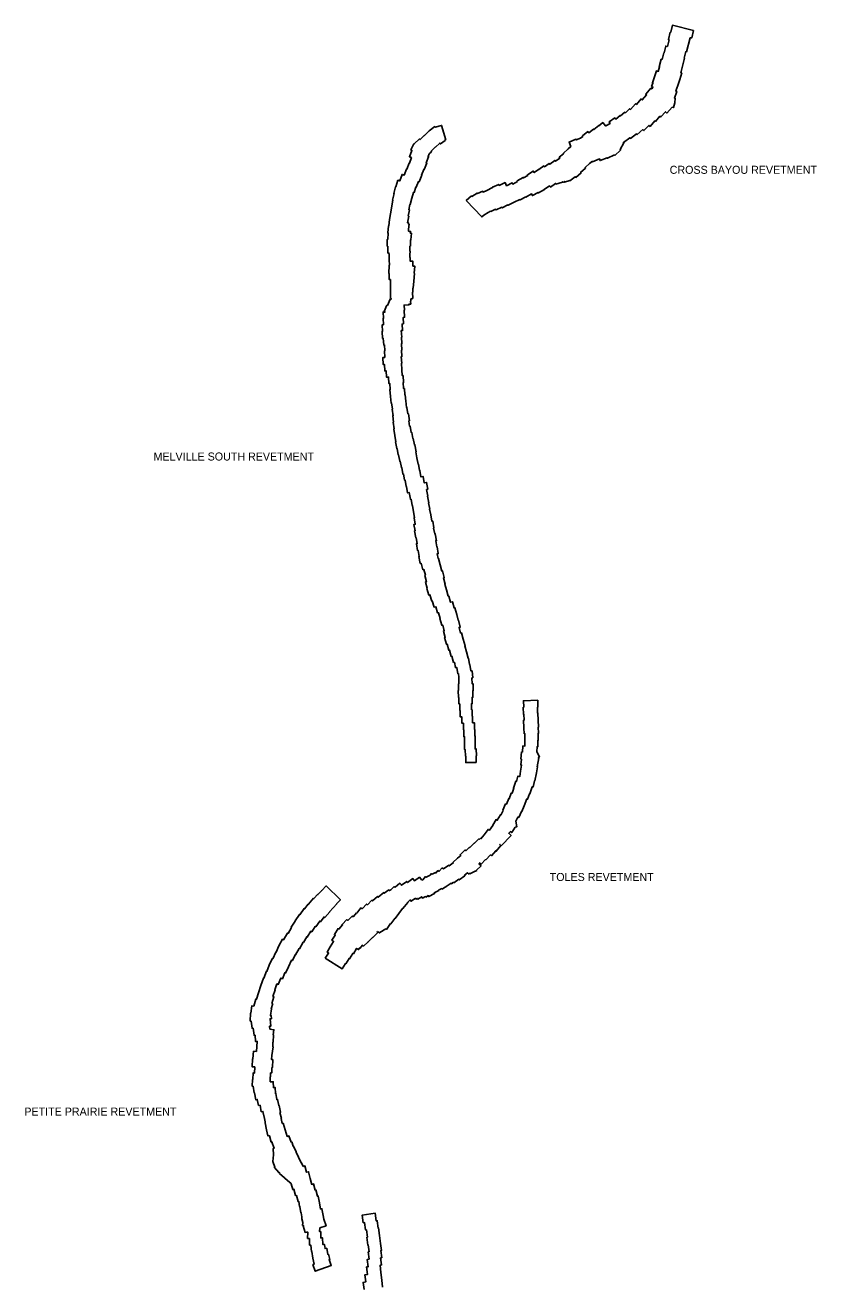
# Model space of a CAD drawing. Extents: x 2650582 to 3923188, y 277893 to 989177.
# Drawn here: x 3142897 to 3158735, y 764129 to 789359 of the extents above; entities that cross this region are included whole.
import ezdxf

# ---------------------------------------------------------------- set-up
doc = ezdxf.new("R2010")
doc.units = 0
doc.layers.add('Level 3', color=7, linetype='Continuous')

msp = doc.modelspace()

# ---------------------------------------------------------------- linework, layer by layer
at = {"layer": 'Level 3'}
for points in [[(3156270, 789256), (3156233, 789104), (3156204, 789110), (3156131, 788828), (3156112, 788832), (3156081, 788702), (3156086, 788701), (3156012, 788410), (3156033, 788404), (3155998, 788277), (3155956, 788154), (3155952, 788156), (3155914, 788044), (3155935, 788036), (3155887, 787901), (3155905, 787899), (3155896, 787808), (3155893, 787809), (3155866, 787712), (3155842, 787718), (3155738, 787601), (3155708, 787628), (3155616, 787524), (3155598, 787540), (3155507, 787434), (3155495, 787444), (3155400, 787335), (3155376, 787355), (3155275, 787251), (3155253, 787272), (3155141, 787171), (3155128, 787185), (3155011, 787094), (3154998, 787110), (3154865, 787014), (3154876, 787008), (3154801, 786871), (3154809, 786863), (3154697, 786755), (3154687, 786765), (3154546, 786699), (3154540, 786710), (3154401, 786653), (3154389, 786684), (3154250, 786627), (3154246, 786639)], [(3154506, 787347), (3154511, 787350), (3154514, 787344), (3154601, 787396), (3154580, 787425), (3154693, 787507), (3154712, 787481), (3154803, 787552), (3154810, 787544), (3154894, 787620), (3154911, 787608), (3154989, 787689), (3155011, 787677), (3155110, 787790), (3155127, 787775), (3155221, 787885), (3155243, 787866), (3155330, 787965), (3155313, 787980), (3155418, 788098), (3155433, 788084), (3155456, 788123), (3155429, 788134), (3155455, 788203), (3155446, 788206), (3155527, 788446), (3155564, 788434), (3155590, 788527), (3155583, 788529), (3155622, 788679), (3155641, 788674), (3155674, 788805), (3155679, 788804), (3155713, 788942), (3155748, 788934), (3155781, 789067), (3155767, 789071), (3155804, 789220), (3155812, 789218), (3155846, 789359), (3156270, 789256)], [(3150217, 783872), (3150217, 783896), (3150208, 783896), (3150206, 784161), (3150207, 784161), (3150205, 784274), (3150182, 784273), (3150179, 784392), (3150175, 784392), (3150177, 784559), (3150184, 784559), (3150181, 784669), (3150179, 784669), (3150178, 784786), (3150174, 784786), (3150174, 784802), (3150154, 784802), (3150152, 784938), (3150140, 784938), (3150142, 785075), (3150151, 785075), (3150157, 785205), (3150152, 785205), (3150165, 785347), (3150171, 785346), (3150189, 785471), (3150185, 785472), (3150206, 785586), (3150252, 785860), (3150245, 785862), (3150277, 785992), (3150272, 785993), (3150308, 786130), (3150311, 786129), (3150353, 786259), (3150392, 786247), (3150439, 786374), (3150477, 786360), (3150527, 786483), (3150534, 786480), (3150581, 786603), (3150584, 786602), (3150626, 786711), (3150584, 786728), (3150635, 786855), (3150614, 786866), (3150674, 786987), (3150681, 786984), (3150788, 787084), (3150798, 787073), (3150883, 787156), (3150886, 787153), (3150979, 787245), (3151092, 787331), (3151101, 787319), (3151227, 787357), (3151315, 787068)], [(3152748, 786231), (3152739, 786247), (3152862, 786314), (3152867, 786305), (3152953, 786355), (3152944, 786369), (3153063, 786442), (3153081, 786413), (3153170, 786476), (3153172, 786473), (3153273, 786545), (3153288, 786525), (3153380, 786595), (3153392, 786580), (3153495, 786657), (3153510, 786638), (3153595, 786702), (3153582, 786718), (3153670, 786790), (3153664, 786797), (3153761, 786884), (3153759, 786887), (3153815, 786936), (3153779, 787021), (3153917, 787079), (3153923, 787064), (3154011, 787101), (3154054, 787136), (3154046, 787145), (3154154, 787233), (3154176, 787207), (3154268, 787281), (3154276, 787272), (3154373, 787351), (3154373, 787350), (3154452, 787413), (3154506, 787347)], [(3151315, 787068), (3151296, 787062), (3151300, 787056), (3151205, 786984), (3151190, 787003), (3151107, 786921), (3151104, 786924), (3151018, 786839), (3151028, 786828), (3150982, 786785), (3150957, 786733), (3150969, 786728), (3150919, 786607), (3150931, 786602), (3150880, 786471), (3150871, 786474), (3150827, 786361), (3150833, 786358), (3150779, 786227), (3150764, 786233), (3150722, 786118), (3150712, 786122), (3150677, 786012), (3150664, 786016), (3150634, 785901), (3150602, 785774), (3150594, 785776), (3150576, 785669), (3150583, 785668), (3150562, 785541), (3150570, 785540), (3150547, 785410), (3150567, 785407), (3150564, 785381), (3150582, 785378), (3150567, 785283), (3150564, 785242), (3150607, 785236), (3150601, 785200)], [(3154246, 786639), (3154189, 786592), (3154099, 786513), (3154109, 786501), (3154011, 786415), (3154021, 786404), (3153913, 786315), (3153902, 786328), (3153796, 786248), (3153791, 786255), (3153688, 786219), (3153683, 786234), (3153658, 786215), (3153648, 786229), (3153650, 786221), (3153516, 786181), (3153512, 786193), (3153510, 786196), (3153409, 786122), (3153404, 786129), (3153403, 786128), (3153399, 786133), (3153396, 786132), (3153388, 786144), (3153284, 786077), (3153285, 786076), (3153166, 786004), (3153158, 786016), (3153047, 785952), (3153028, 785985), (3152915, 785923), (3152914, 785925)], [(3152914, 785925), (3152798, 785866), (3152794, 785873), (3152682, 785818), (3152559, 785760), (3152557, 785764), (3152441, 785707), (3152435, 785719), (3152317, 785664), (3152310, 785678), (3152212, 785635), (3152210, 785639), (3152158, 785616), (3152073, 785563), (3152031, 785524), (3151723, 785851), (3151824, 785945), (3151833, 785937), (3151939, 786003), (3151947, 785991), (3152052, 786038), (3152059, 786023), (3152132, 786055), (3152132, 786056), (3152249, 786111), (3152246, 786118), (3152372, 786177), (3152383, 786156), (3152500, 786211), (3152530, 786149), (3152642, 786204), (3152653, 786183), (3152748, 786231)], [(3150601, 785200), (3150623, 785199), (3150614, 785066), (3150609, 785067), (3150604, 784942), (3150596, 784943), (3150593, 784839), (3150597, 784839), (3150594, 784765), (3150594, 784715), (3150601, 784714), (3150600, 784684)], [(3150600, 784684), (3150601, 784639), (3150654, 784638), (3150653, 784543), (3150691, 784541), (3150682, 784398), (3150685, 784397), (3150675, 784239), (3150671, 784240), (3150661, 784101), (3150651, 784102)], [(3150651, 784102), (3150653, 784024), (3150648, 784024), (3150650, 783895), (3150633, 783895), (3150633, 783885), (3150616, 783885), (3150616, 783843), (3150607, 783843), (3150611, 783783), (3150574, 783781), (3150574, 783766), (3150478, 783764), (3150485, 783658), (3150478, 783658), (3150488, 783519), (3150460, 783517), (3150468, 783386)], [(3150068, 783368), (3150059, 783498), (3150067, 783499), (3150058, 783621), (3150097, 783623), (3150078, 783632), (3150133, 783760), (3150144, 783756), (3150198, 783881), (3150217, 783872)], [(3150468, 783386), (3150439, 783384), (3150448, 783253), (3150421, 783251), (3150431, 783121), (3150427, 783121), (3150436, 782991), (3150424, 782990), (3150433, 782861), (3150425, 782860), (3150434, 782731), (3150420, 782729), (3150430, 782600), (3150426, 782599), (3150435, 782470), (3150433, 782470), (3150442, 782351), (3150457, 782352), (3150468, 782212), (3150459, 782211), (3150468, 782091), (3150484, 782092), (3150494, 781965), (3150501, 781965), (3150510, 781844), (3150513, 781845), (3150529, 781714), (3150534, 781715), (3150550, 781587)], [(3150258, 781550), (3150242, 781679), (3150243, 781679), (3150227, 781805), (3150219, 781804), (3150209, 781933), (3150206, 781933), (3150196, 782072), (3150201, 782073), (3150193, 782193), (3150176, 782192), (3150167, 782321), (3150127, 782318), (3150118, 782448), (3150092, 782446), (3150083, 782576), (3150062, 782574), (3150052, 782714), (3150091, 782717), (3150083, 782847), (3150091, 782847), (3150083, 782967), (3150071, 782966), (3150062, 783096), (3150048, 783096), (3150038, 783235), (3150049, 783236), (3150039, 783365), (3150068, 783368)], [(3150618, 779881), (3150605, 779878), (3150581, 780012), (3150549, 780006), (3150527, 780134), (3150522, 780133), (3150499, 780261), (3150488, 780259), (3150465, 780387), (3150452, 780385), (3150430, 780513), (3150425, 780512), (3150402, 780640), (3150391, 780638), (3150368, 780766), (3150360, 780765), (3150337, 780893), (3150331, 780892), (3150308, 781029), (3150312, 781030), (3150290, 781157), (3150293, 781157), (3150270, 781284), (3150279, 781286), (3150262, 781420), (3150268, 781421), (3150252, 781549), (3150258, 781550)], [(3150550, 781587), (3150566, 781588), (3150584, 781450), (3150573, 781449), (3150587, 781339), (3150597, 781341), (3150619, 781215), (3150631, 781217), (3150654, 781091), (3150662, 781092), (3150684, 780966), (3150693, 780968), (3150718, 780829), (3150711, 780827), (3150732, 780709), (3150757, 780582), (3150764, 780583), (3150788, 780456), (3150793, 780456), (3150816, 780327), (3150857, 780335), (3150880, 780207), (3150927, 780215), (3150952, 780078), (3150929, 780073), (3150953, 779942), (3150949, 779941)], [(3150940, 778099), (3150906, 778224), (3150926, 778229), (3150893, 778355), (3150906, 778358), (3150875, 778474), (3150855, 778468), (3150820, 778599), (3150801, 778596), (3150776, 778734), (3150781, 778734), (3150761, 778853), (3150748, 778851), (3150725, 778990), (3150740, 778992), (3150719, 779110), (3150711, 779108), (3150686, 779246), (3150699, 779248), (3150676, 779376), (3150700, 779380), (3150678, 779508), (3150689, 779510), (3150645, 779754), (3150640, 779753), (3150618, 779881)], [(3150949, 779941), (3150972, 779810), (3150969, 779809), (3150991, 779682), (3150989, 779682), (3151010, 779566), (3151013, 779566), (3151035, 779440), (3151051, 779442), (3151075, 779305), (3151069, 779304), (3151090, 779186), (3151102, 779189), (3151127, 779050), (3151113, 779048), (3151134, 778929), (3151138, 778930), (3151161, 778792), (3151142, 778789), (3151159, 778695), (3151164, 778696), (3151231, 778444), (3151246, 778448), (3151283, 778314), (3151265, 778309), (3151299, 778184)], [(3151554, 776390), (3151531, 776517), (3151505, 776512), (3151486, 776620), (3151468, 776615), (3151434, 776741), (3151422, 776737), (3151388, 776863), (3151372, 776859), (3151338, 776982), (3151324, 776979), (3151287, 777114), (3151300, 777117), (3151266, 777243), (3151282, 777248), (3151250, 777364), (3151231, 777359), (3151194, 777494), (3151199, 777495), (3151168, 777610), (3151148, 777605), (3151114, 777730), (3151077, 777721), (3151043, 777847), (3151030, 777843), (3150996, 777969), (3150971, 777961), (3150934, 778097), (3150940, 778099)], [(3151299, 778184), (3151292, 778183), (3151324, 778067), (3151328, 778069), (3151363, 777941), (3151372, 777944), (3151407, 777819), (3151444, 777829), (3151478, 777705), (3151495, 777710), (3151532, 777574), (3151530, 777574), (3151562, 777458), (3151566, 777459), (3151602, 777324), (3151578, 777317), (3151610, 777201), (3151628, 777206), (3151661, 777081), (3151663, 777082), (3151699, 776947), (3151695, 776946), (3151726, 776831), (3151727, 776831), (3151763, 776700), (3151765, 776701), (3151787, 776572), (3151792, 776573), (3151815, 776445), (3151839, 776448)], [(3151839, 776448), (3151853, 776309), (3151836, 776307), (3151838, 776190), (3151858, 776191), (3151861, 776050), (3151852, 776050), (3151854, 775920), (3151840, 775920), (3151843, 775790), (3151825, 775789), (3151828, 775671), (3151840, 775671), (3151843, 775541), (3151848, 775541), (3151850, 775409), (3151884, 775410), (3151887, 775275), (3151892, 775275), (3151893, 775145), (3151899, 775145), (3151901, 775005), (3151898, 775005), (3151899, 774886), (3151923, 774886), (3151924, 774746), (3151919, 774745), (3151920, 774615), (3151712, 774613), (3151711, 774743), (3151704, 774743), (3151703, 774873), (3151689, 774873), (3151688, 775013), (3151689, 775013), (3151689, 775132), (3151673, 775132), (3151672, 775268), (3151667, 775267), (3151665, 775398), (3151636, 775398), (3151634, 775527), (3151600, 775527), (3151598, 775656), (3151595, 775656), (3151592, 775786), (3151575, 775786), (3151573, 775916), (3151564, 775915), (3151562, 776056), (3151566, 776056), (3151564, 776185), (3151571, 776186), (3151570, 776314), (3151574, 776314), (3151565, 776392), (3151554, 776390)], [(3153152, 775861), (3152866, 775849), (3152872, 775721), (3152863, 775721), (3152867, 775577), (3152877, 775578), (3152880, 775459), (3152867, 775459), (3152873, 775307), (3152876, 775307), (3152881, 775189), (3152895, 775189), (3152897, 775059), (3152894, 774944), (3152857, 774946), (3152849, 774823), (3152828, 774825), (3152816, 774682), (3152828, 774681), (3152811, 774566), (3152830, 774563), (3152807, 774442), (3152810, 774441), (3152791, 774334), (3152754, 774342), (3152729, 774237), (3152713, 774243), (3152664, 774103), (3152673, 774100), (3152638, 773998), (3152622, 774004), (3152581, 773888), (3152571, 773892), (3152525, 773779), (3152510, 773785), (3152454, 773658), (3152458, 773657), (3152412, 773563), (3152405, 773568), (3152341, 773460), (3152319, 773473), (3152251, 773358), (3152255, 773356), (3152190, 773262), (3152158, 773276), (3152077, 773171), (3152016, 773091), (3152005, 773100), (3151983, 773076), (3151973, 773086), (3151885, 772999), (3151882, 773002), (3151791, 772914), (3151787, 772919), (3151715, 772850), (3151698, 772865), (3151597, 772771), (3151612, 772754), (3151549, 772698), (3151455, 772616), (3151463, 772607), (3151381, 772545), (3151371, 772558), (3151266, 772488), (3151241, 772510)], [(3153144, 775723), (3153157, 775724), (3153152, 775861)], [(3151471, 772207), (3151573, 772279), (3151583, 772266), (3151694, 772351), (3151689, 772358), (3151746, 772408), (3151766, 772385), (3151785, 772400), (3151791, 772387), (3151902, 772442), (3151906, 772438), (3151919, 772450), (3151931, 772456), (3151929, 772460), (3152019, 772545), (3151975, 772591), (3151992, 772609), (3152019, 772582), (3152110, 772672), (3152113, 772669), (3152207, 772766), (3152225, 772750), (3152312, 772849), (3152322, 772841), (3152411, 772957), (3152393, 772972), (3152396, 772976), (3152421, 772951), (3152619, 773153), (3152571, 773200), (3152604, 773233), (3152632, 773214), (3152703, 773321), (3152731, 773325), (3152713, 773439), (3152719, 773453), (3152754, 773524), (3152773, 773516), (3152827, 773637), (3152832, 773635), (3152878, 773747), (3152881, 773746), (3152931, 773886), (3152950, 773880), (3152988, 773991), (3152994, 773989), (3153043, 774128), (3153060, 774124), (3153090, 774250), (3153096, 774249), (3153127, 774411), (3153148, 774528), (3153143, 774529), (3153175, 774711), (3153163, 774714), (3153185, 774724), (3153133, 774834), (3153140, 774928), (3153152, 774927), (3153154, 775061), (3153163, 775061), (3153162, 775199), (3153168, 775199), (3153163, 775318), (3153166, 775318), (3153155, 775602), (3153148, 775602), (3153144, 775723)], [(3150830, 772258), (3150783, 772321), (3150685, 772248), (3150652, 772292), (3150548, 772214), (3150530, 772237), (3150427, 772160), (3150419, 772174), (3150417, 772172), (3150393, 772201), (3150297, 772123), (3150295, 772125), (3150291, 772121), (3150281, 772132), (3150210, 772068), (3150186, 772052), (3150175, 772067), (3150081, 772001), (3150071, 772013), (3149960, 771919), (3149943, 771937), (3149848, 771846), (3149835, 771859), (3149835, 771859), (3149834, 771859), (3149745, 771771), (3149743, 771774), (3149740, 771771), (3149724, 771784), (3149645, 771694), (3149638, 771701), (3149629, 771693), (3149610, 771707), (3149531, 771602), (3149527, 771605), (3149502, 771573), (3149458, 771528), (3149442, 771543), (3149354, 771455), (3149335, 771474), (3149236, 771375), (3149246, 771365), (3149174, 771283), (3149157, 771293), (3149083, 771174), (3149100, 771164), (3149034, 771058), (3149066, 771037), (3149000, 770931), (3149002, 770930), (3148936, 770824), (3148967, 770804), (3148901, 770698)], [(3151241, 772510), (3151181, 772441), (3151180, 772443), (3151172, 772438), (3151156, 772453), (3151110, 772403), (3151105, 772413), (3151043, 772382), (3151029, 772394), (3150997, 772358), (3150923, 772320), (3150909, 772333), (3150850, 772268), (3150830, 772258)], [(3147471, 769743), (3147509, 769884), (3147526, 769880), (3147566, 770010), (3147563, 770011), (3147612, 770152), (3147610, 770153), (3147664, 770304), (3147671, 770301), (3147726, 770439), (3147729, 770437), (3147777, 770561), (3147780, 770560), (3147838, 770691), (3147851, 770685), (3147911, 770820), (3147916, 770818), (3147975, 770945), (3148048, 771081), (3148068, 771070), (3148144, 771204), (3148156, 771197), (3148223, 771316), (3148221, 771318), (3148298, 771444), (3148296, 771445), (3148382, 771576), (3148390, 771571), (3148478, 771693), (3148487, 771687), (3148562, 771784), (3148567, 771780), (3148667, 771898), (3148674, 771892), (3148749, 771979), (3148754, 771974), (3148832, 772056), (3148830, 772057), (3148918, 772147), (3149204, 771868), (3149127, 771790), (3149132, 771785), (3148986, 771631), (3148989, 771628), (3148892, 771513), (3148878, 771525), (3148806, 771431), (3148790, 771443), (3148711, 771331), (3148702, 771337), (3148630, 771226), (3148612, 771238), (3148542, 771123), (3148530, 771130), (3148464, 771014), (3148458, 771018), (3148384, 770889), (3148376, 770894), (3148307, 770765), (3148298, 770770), (3148244, 770652), (3148225, 770661), (3148166, 770527), (3148162, 770528), (3148107, 770404), (3148091, 770411), (3148044, 770291), (3148010, 770304), (3147959, 770175), (3147934, 770185), (3147892, 770069), (3147898, 770067), (3147852, 769935), (3147875, 769928), (3147834, 769797), (3147850, 769793)], [(3150590, 771859), (3150602, 771866), (3150618, 771841), (3150705, 771898), (3150713, 771882), (3150744, 771897), (3150754, 771880), (3150833, 771929), (3150845, 771903), (3150909, 771934), (3150918, 771922), (3150960, 771953), (3150971, 771933), (3151088, 771993), (3151080, 772008), (3151170, 772055), (3151167, 772060), (3151234, 772094), (3151241, 772084), (3151307, 772127), (3151311, 772124), (3151323, 772137), (3151417, 772198), (3151431, 772186), (3151461, 772221), (3151471, 772207)], [(3149949, 771233), (3149988, 771205), (3149994, 771213), (3150110, 771286), (3150125, 771275), (3150209, 771393), (3150216, 771388), (3150295, 771495), (3150298, 771493), (3150446, 771695), (3150450, 771692), (3150554, 771812), (3150549, 771816), (3150590, 771859)], [(3148901, 770698), (3149238, 770487), (3149305, 770593), (3149310, 770590), (3149376, 770696), (3149386, 770690), (3149452, 770796), (3149463, 770789), (3149529, 770895), (3149566, 770872), (3149585, 770902), (3149591, 770896), (3149649, 770962), (3149668, 770943), (3149756, 771031), (3149760, 771027), (3149849, 771115), (3149851, 771114), (3149950, 771213), (3149939, 771223), (3149949, 771233)], [(3147850, 769793), (3147821, 769686), (3147826, 769686), (3147805, 769553), (3147821, 769553), (3147823, 769491), (3147798, 769490), (3147815, 769344), (3147785, 769341), (3147794, 769280)], [(3147526, 768833), (3147540, 769036), (3147508, 769033), (3147496, 769161), (3147477, 769158), (3147455, 769301), (3147436, 769298), (3147418, 769442), (3147400, 769443), (3147402, 769601), (3147410, 769601), (3147434, 769748), (3147471, 769743)], [(3147794, 769280), (3147873, 769269), (3147859, 769167), (3147867, 769167), (3147861, 769023), (3147853, 769024), (3147849, 768932), (3147857, 768931)], [(3147491, 768526), (3147441, 768527), (3147447, 768687), (3147452, 768687), (3147467, 768839), (3147526, 768833)], [(3147857, 768931), (3147835, 768756), (3147827, 768674), (3147851, 768673), (3147845, 768514), (3147832, 768514), (3147829, 768408), (3147808, 768408), (3147805, 768326), (3147796, 768326), (3147799, 768263), (3147801, 768263), (3147800, 768227)], [(3147839, 767023), (3147837, 767028), (3147821, 767023), (3147783, 767151), (3147773, 767148), (3147771, 767153), (3147752, 767148), (3147725, 767266), (3147722, 767266), (3147698, 767411), (3147700, 767411), (3147696, 767429), (3147700, 767430), (3147688, 767495), (3147682, 767494), (3147654, 767638), (3147621, 767631), (3147595, 767761), (3147565, 767755), (3147541, 767875), (3147512, 767868), (3147482, 768006), (3147480, 768005), (3147455, 768139), (3147440, 768139), (3147444, 768273), (3147450, 768272), (3147456, 768405), (3147486, 768404), (3147491, 768526)], [(3147800, 768227), (3147859, 768230), (3147865, 768113), (3147896, 768115), (3147904, 767994), (3147913, 767996), (3147930, 767873), (3147948, 767876), (3147969, 767752), (3147980, 767754), (3148007, 767621), (3147994, 767618), (3148022, 767496), (3148016, 767494), (3148041, 767395), (3148057, 767400), (3148097, 767265)], [(3148097, 767265), (3148100, 767266), (3148141, 767135), (3148172, 767147), (3148218, 767022), (3148229, 767026), (3148259, 766942), (3148264, 766944), (3148319, 766825), (3148316, 766823), (3148363, 766723), (3148366, 766724), (3148420, 766606), (3148425, 766608), (3148457, 766538)], [(3148201, 766219), (3148195, 766213), (3148095, 766304), (3148092, 766303), (3148088, 766311), (3147985, 766397), (3147988, 766400), (3147978, 766419), (3147969, 766412), (3147885, 766516), (3147891, 766521), (3147853, 766637), (3147862, 766766), (3147865, 766766), (3147861, 766893), (3147866, 766894), (3147865, 766896), (3147878, 766901), (3147833, 767021), (3147839, 767023)], [(3148457, 766538), (3148495, 766546), (3148527, 766421), (3148566, 766430), (3148600, 766294), (3148598, 766293), (3148623, 766196), (3148631, 766178), (3148666, 766187), (3148697, 766062), (3148713, 766065), (3148744, 765940), (3148761, 765943), (3148786, 765805), (3148783, 765804), (3148804, 765686), (3148833, 765691), (3148857, 765554), (3148856, 765553), (3148873, 765483), (3148916, 765350), (3148790, 765309)], [(3148502, 765216), (3148459, 765349), (3148465, 765351), (3148464, 765356), (3148447, 765356), (3148449, 765415), (3148432, 765485), (3148434, 765485), (3148434, 765529), (3148420, 765609), (3148415, 765608), (3148392, 765736), (3148387, 765735), (3148369, 765835), (3148356, 765832), (3148325, 765958), (3148306, 765953), (3148274, 766080), (3148249, 766073), (3148221, 766188), (3148214, 766199), (3148206, 766197), (3148201, 766219)], [(3149678, 764072), (3149658, 764217), (3149715, 764230), (3149694, 764370), (3149747, 764378), (3149729, 764527), (3149761, 764531), (3149742, 764677), (3149779, 764682), (3149760, 764827), (3149779, 764829), (3149761, 764965), (3149753, 764964), (3149733, 765120), (3149743, 765121), (3149724, 765267), (3149709, 765265), (3149688, 765414), (3149661, 765411), (3149641, 765564), (3149900, 765599), (3149920, 765448), (3149941, 765451), (3149961, 765304), (3149964, 765305), (3149983, 765152), (3149989, 765153), (3150008, 764996), (3150004, 764996), (3150023, 764853), (3150012, 764852), (3150031, 764709), (3150009, 764706), (3150027, 764565), (3149997, 764561), (3150015, 764414), (3150011, 764414), (3150033, 764263), (3150030, 764262), (3150049, 764119)], [(3148790, 765309), (3148788, 765233), (3148811, 765232), (3148809, 765106), (3148846, 765106), (3148849, 764978), (3148887, 764973), (3148897, 764893), (3148929, 764899), (3148950, 764776), (3148964, 764779), (3148990, 764676), (3148977, 764673), (3149020, 764558), (3148701, 764441), (3148653, 764572), (3148682, 764583), (3148652, 764702), (3148654, 764702), (3148631, 764833), (3148627, 764833), (3148612, 764963), (3148588, 764962), (3148585, 765094), (3148548, 765095), (3148551, 765224), (3148528, 765224), (3148502, 765216)]]:
    msp.add_lwpolyline(points, dxfattribs=at)

# ---------------------------------------------------------------- texts
for s, p in [('CROSS BAYOU REVETMENT', (3155792, 786388)), ('MELVILLE SOUTH REVETMENT', (3145465, 780654)), ('TOLES REVETMENT', (3153392, 772245)), ('PETITE PRAIRIE REVETMENT', (3142880, 767553))]:
    msp.add_text(s, height=160, dxfattribs=at).set_placement(p)

doc.saveas('drawing.dxf')
